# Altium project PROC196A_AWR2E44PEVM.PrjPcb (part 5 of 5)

## Sheet PROC196A_CAN_Interface.SchDoc
size 431 x 279 mm; Date: Not shown in title block; ApprovedBy: Not shown in title block; CheckedBy: Not shown in title block; Author: Not shown in title block; CompanyName: Not shown in title block; Engineer: Not shown in title block; Organization: Not shown in title block; Address1: Not shown in title block; Address2: Not shown in title block; Address3: Not shown in title block; Address4: Not shown in title block; DocumentNumber: 22; Revision: Use project parameter SCH_Rev; SheetNumber: 22; SheetTotal: 25; PageSetup: Record=PageOptions¦CenterHorizontal=True¦CenterVertical=True¦PrintScale=1.00¦XCorrection=1.00¦YCorrection=1.00¦PrintKind=0¦BorderSize=5000000¦LeftOffset=0¦BottomOffset=0¦Orientation=2¦PaperLength=1000¦PaperWidth=1000¦Scale=100¦PaperSource=15¦PrintQuality=600¦MediaType=1¦DitherType=10¦PaperKind=Letter¦PrintScaleMode=1
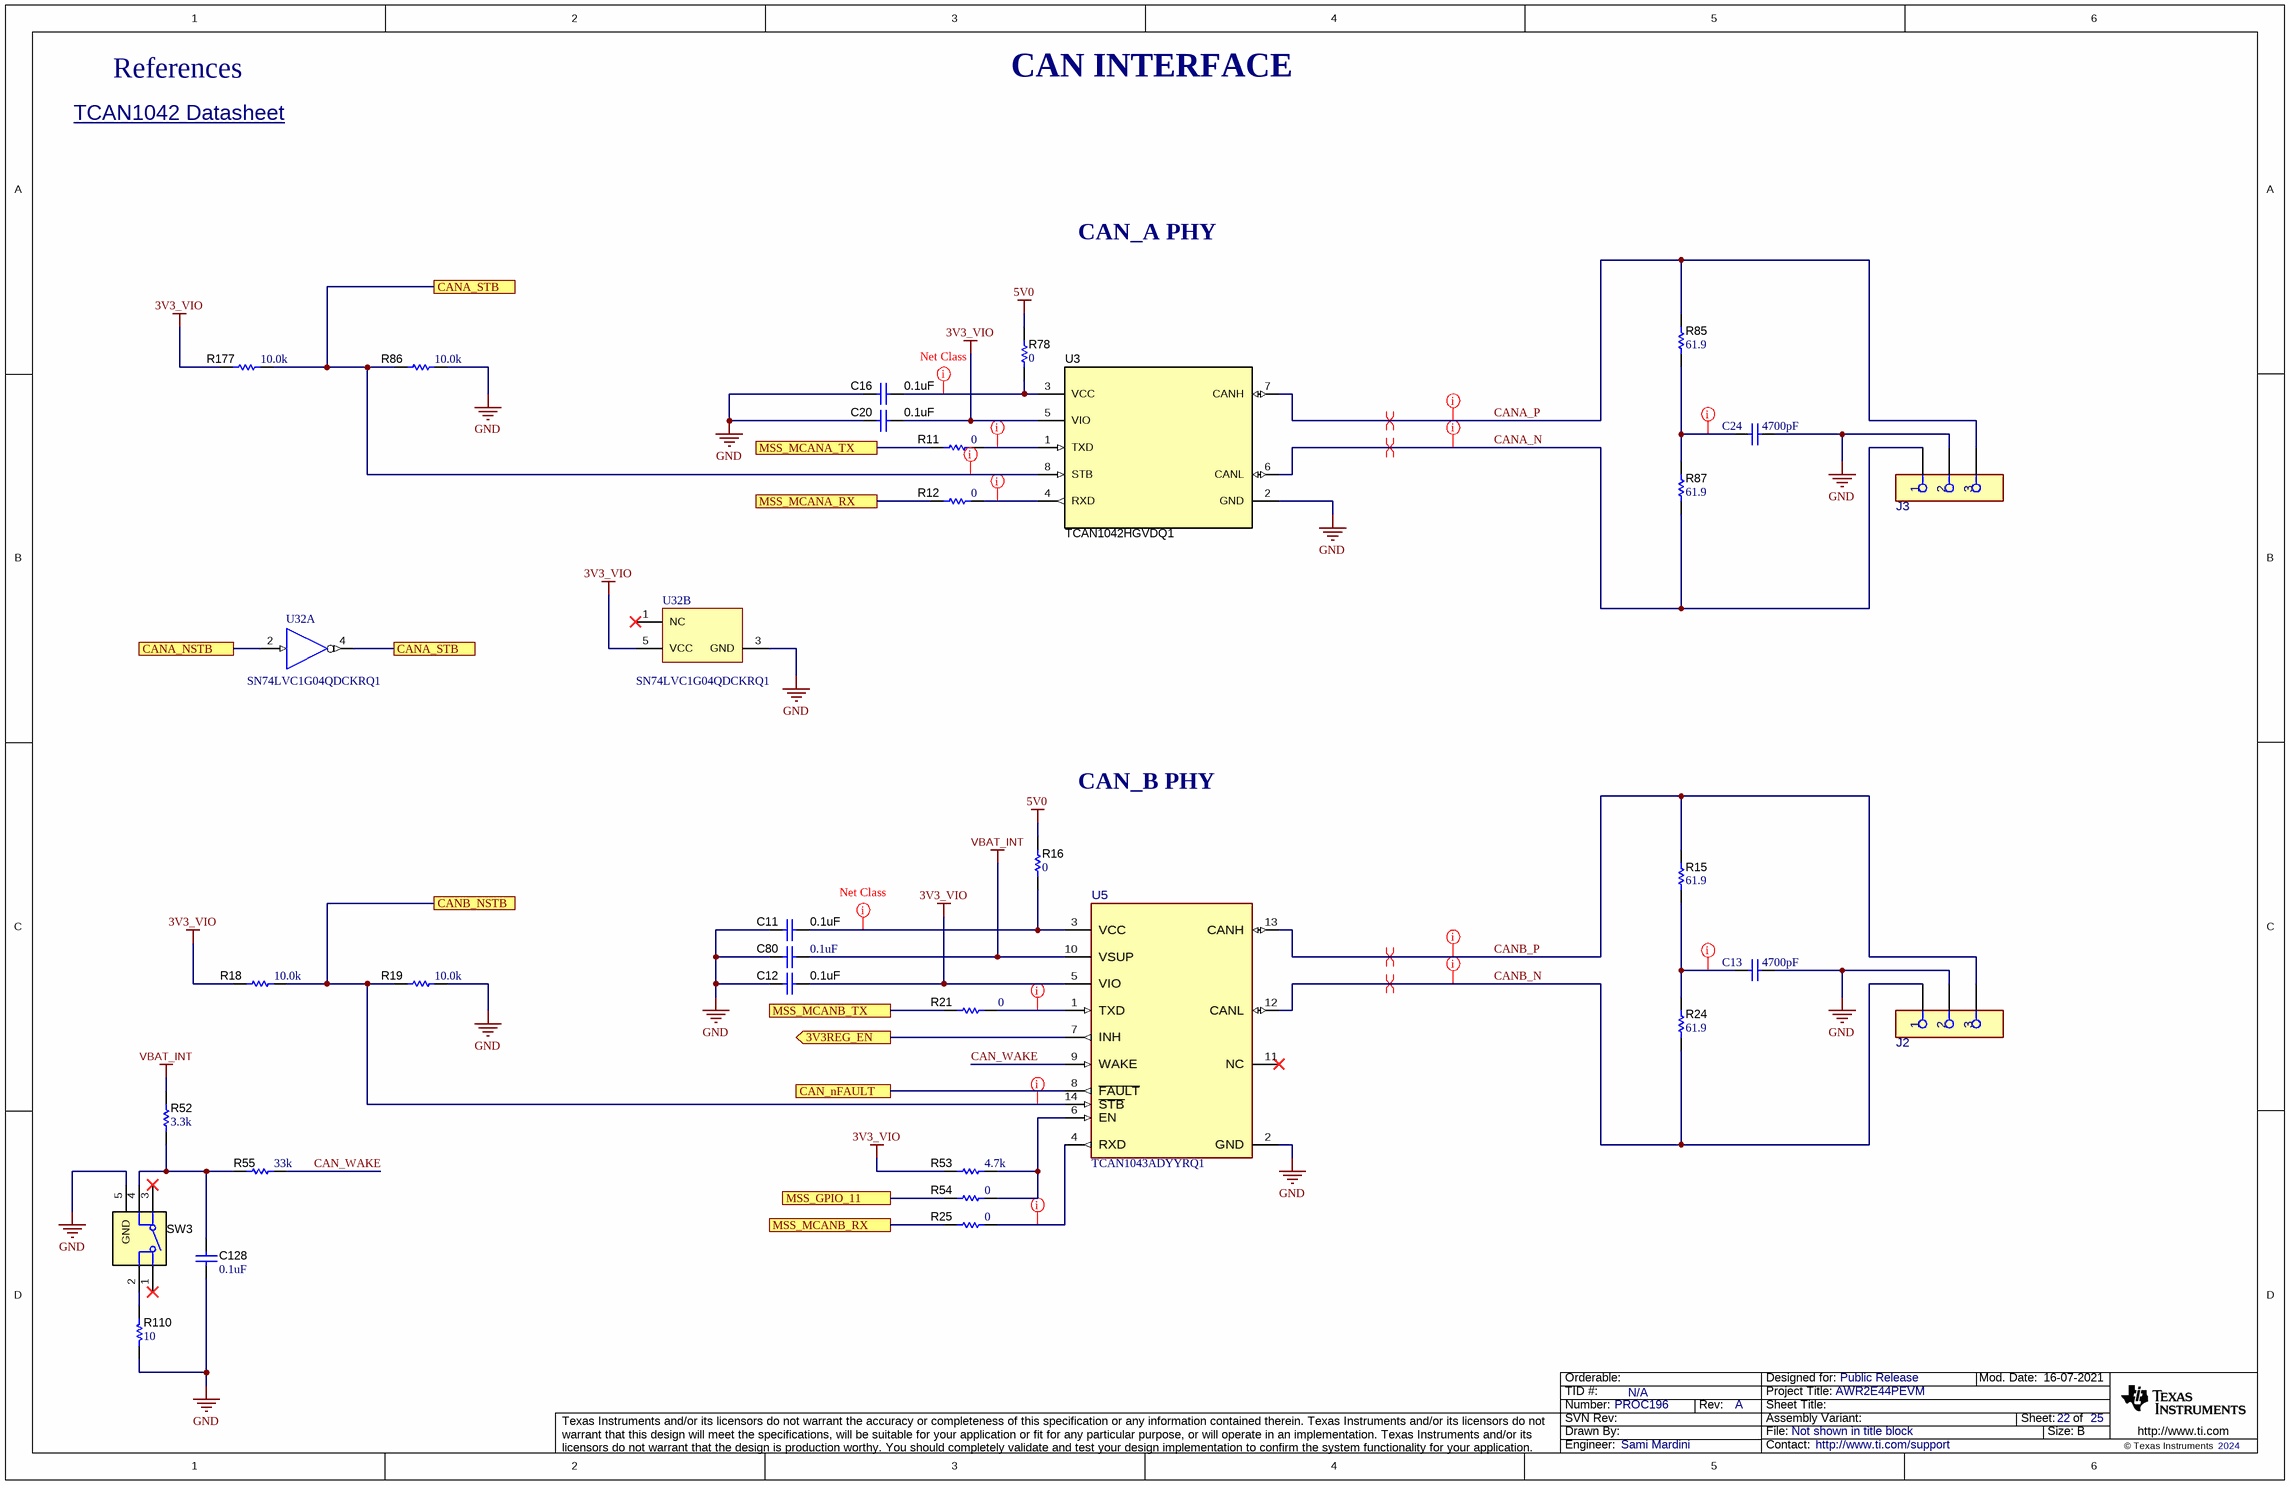
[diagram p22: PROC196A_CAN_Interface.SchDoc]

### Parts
C11  ValueDisplayed: 0.1uF  [0402L]  (hidden comment: GCM155R71C104KA55D)
C12  ValueDisplayed: 0.1uF  [0402L]  (hidden comment: GCM155R71C104KA55D)
C13  ValueDisplayed: 4700pF  [0402L]  (hidden comment: GCM155R71H472KA37D)
C16  ValueDisplayed: 0.1uF  [0402L]  (hidden comment: GCM155R71C104KA55D)
C20  ValueDisplayed: 0.1uF  [0402L]  (hidden comment: GCM155R71C104KA55D)
C24  ValueDisplayed: 4700pF  [0402L]  (hidden comment: GCM155R71H472KA37D)
C80  ValueDisplayed: 0.1uF  [0402L]  (hidden comment: CGA2B3X7R1H104K050BB)
C128  ValueDisplayed: 0.1uF  [0402L]  (hidden comment: CGA2B3X7R1H104K050BB)
J2  OSTTF030161  [FP-OSTTF030161_PTH_TERMINAL_BLOCK-MFG]  (value not drawn)
J3  OSTTF030161  [FP-OSTTF030161_PTH_TERMINAL_BLOCK-MFG]  (value not drawn)
R11  value 0  [0402L]  (hidden comment: ERJ-2GE0R00X)
R12  ValueDisplayed: 0  [0402L]  (hidden comment: ERJ-2GE0R00X)
R15  ValueDisplayed: 61.9  [0402L]  (hidden comment: CRCW040261R9FKED)
R16  ValueDisplayed: 0  [0402L]  (hidden comment: ERJ-2GE0R00X)
R18  ValueDisplayed: 10.0k  [0402L]  (hidden comment: CRCW040210K0FKED)
R19  ValueDisplayed: 10.0k  [0402L]  (hidden comment: CRCW040210K0FKED)
R21  value 0  [0402L]  (hidden comment: ERJ-2GE0R00X)
R24  ValueDisplayed: 61.9  [0402L]  (hidden comment: CRCW040261R9FKED)
R25  ValueDisplayed: 0  [0402L]  (hidden comment: ERJ-2GE0R00X)
R52  ValueDisplayed: 3.3k  [0402L]  (hidden comment: CRCW04023K30JNED)
R53  ValueDisplayed: 4.7k  [0402L]  (hidden comment: CRCW04024K70JNED)
R54  ValueDisplayed: 0  [0402L]  (hidden comment: ERJ-2GE0R00X)
R55  ValueDisplayed: 33k  [0402L]  (hidden comment: CRCW040233K0JNED)
R78  ValueDisplayed: 0  [0402L]  (hidden comment: ERJ-2GE0R00X)
R85  ValueDisplayed: 61.9  [0402L]  (hidden comment: CRCW040261R9FKED)
R86  ValueDisplayed: 10.0k  [0402L]  (hidden comment: CRCW040210K0FKED)
R87  ValueDisplayed: 61.9  [0402L]  (hidden comment: CRCW040261R9FKED)
R110  ValueDisplayed: 10  [0402L]  (hidden comment: CRCW040210R0JNED)
R177  ValueDisplayed: 10.0k  [0402L]  (hidden comment: CRCW040210K0FKED)
SW3  KMR243GLFG  [SW_KMR243GLFG]  (value not drawn)
U3  TCAN1042HGVDQ1  [D0008A_L]
U5  TCAN1043ADYYRQ1  [DYY0014A-MFG]
U32  SN74LVC1G04QDCKRQ1  [DCK0005A_N]  (parts A,B of 2)

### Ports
3V3REG_EN (out), CAN_nFAULT, CANA_NSTB, CANA_STB, CANB_NSTB, MSS_GPIO_11, MSS_MCANA_RX, MSS_MCANA_TX, MSS_MCANB_RX, MSS_MCANB_TX

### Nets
3V3_VIO: C12.2 C20.2 R18.1 R53.1 R177.1 U3.5(VIO) U5.5(VIO) U32.5(VCC)
5V0: R16.2 R78.2
GND: C11.1 C12.1 C13.1 C16.1 C20.1 C24.1 C80.2 C128.2 J2.2 J3.2 R19.2 R86.2 R110.1 SW3.5(GND) U3.2(GND) U5.2(GND) U32.3(GND)
VBAT_INT: C80.1 R52.2 U5.10(VSUP)
3V3REG_EN: U5.7(INH) ; port 3V3REG_EN
CAN_nFAULT: U5.8(~{FAULT}) ; port CAN_nFAULT
CAN_WAKE: R55.1 U5.9(WAKE)
CANA_N: J3.1 R87.1 U3.6(CANL)
CANA_NSTB: U32.2(A) ; port CANA_NSTB
CANA_P: J3.3 R85.2 U3.7(CANH)
CANA_STB: R86.1 R177.2 U3.8(STB) U32.4(Y) ; port CANA_STB
CANB_N: J2.1 R24.1 U5.12(CANL)
CANB_NSTB: R18.2 R19.1 U5.14(~{STB}) ; port CANB_NSTB
CANB_P: J2.3 R15.2 U5.13(CANH)
MSS_GPIO_11: R54.1 ; port MSS_GPIO_11
MSS_MCANA_RX: R12.1 ; port MSS_MCANA_RX
MSS_MCANA_TX: R11.1 ; port MSS_MCANA_TX
MSS_MCANB_RX: R25.1 ; port MSS_MCANB_RX
MSS_MCANB_TX: R21.1 ; port MSS_MCANB_TX
NetC11_2: C11.2 R16.1 U5.3(VCC)
NetC13_2: C13.2 R15.1 R24.2
NetC16_2: C16.2 R78.1 U3.3(VCC)
NetC24_2: C24.2 R85.1 R87.2
NetC128_1: C128.1 R52.1 R55.2 SW3.4
NetR11_2: R11.2 U3.1(TXD)
NetR12_2: R12.2 U3.4(RXD)
NetR21_2: R21.2 U5.1(TXD)
NetR25_2: R25.2 U5.4(RXD)
NetR53_2: R53.2 R54.2 U5.6(EN)
NetR110_2: R110.2 SW3.2

Not connected (* = marked no-connect by the designer): SW3 1* 3*; U5 11(NC)*; U32 1(NC)*

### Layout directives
net class CAN: CANA_STB, CANB_NSTB, NetR11_2, NetR12_2, NetR21_2, NetR25_2
net class CAN; net class CAN_DIFF: CANA_N, CANA_P, CANB_N, CANB_P
net class CAN; net class PWR: NetC13_2, NetC24_2
net class PWR: NetC11_2, NetC16_2
differential pair: CANA_N, CANA_P, CANB_N, CANB_P

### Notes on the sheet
- References
- CAN INTERFACE
- TCAN1042 Datasheet <http://www.ti.com/lit/ds/symlink/tcan1042gv-q1.pdf>
- CAN_A PHY
- CAN_B PHY

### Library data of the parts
C11 C12 C16 C20 = CMP-0006351-2: CAP, CERM, 0.1 uF, 16 V, +/- 10%, X7R, 0402; Manufacturer: MuRata; TaMin_C: -55°C; Polarized: N; SizeAreaWB_mm2: 3; Value1: Unknown; U/M: EA; Value: 0.1uF; TaMax_C: 125°C; SizeZ_mm: 0.6; SizeX_mm: 1; SizeY_mm: 0.5; Cap_Case: 0402; Value2: 16V; Cap_F: 100nF; AEC Category: Q200
C13 C24 = CMP-0006361-2: CAP, CERM, 4700 pF, 50 V, +/- 10%, X7R, AEC-Q200 Grade 1, 0402; Manufacturer: MuRata; TaMin_C: -55°C; Polarized: N; SizeAreaWB_mm2: 3; Value1: Unknown; U/M: EA; Value: 4700pF; TaMax_C: 125°C; SizeZ_mm: 0.6; SizeX_mm: 1; SizeY_mm: 0.5; Cap_Case: 0402; Value2: 50V; AEC Qualified: Y; Cap_F: 4.7nF; AEC Category: Q200
C80 C128 = CMP-0006325-2: CAP, CERM, 0.1 uF, 50 V, +/- 10%, X7R, AEC-Q200 Grade 1, 0402; Manufacturer: TDK; TaMin_C: -55°C; ESR_ohm: 0.039064; Polarized: N; SizeAreaWB_mm2: 3; Value1: 0.039064 ohm; U/M: EA; Value: 0.1uF; TaMax_C: 125°C; SizeZ_mm: 0.6; SizeX_mm: 1; SizeY_mm: 0.5; Cap_Case: 0402; Value2: 50V; AEC Qualified: Y; Cap_F: 100nF; IRMS_A: 8.14669dA; AEC Category: Q200
J2 J3 = CMP-0091742-1: 3 Position Wire to Board Terminal Block Vertical with Board 0.138" (3.50mm) Through Hole; Manufacturer: On Shore Technology; Voltage_V: 150V; Row_Count: 1; DUT-Pitch_mm: 3.5mm; Current_A: 10A; Min Wire Gauge: 30; ContactFinish: Tin; AEC Qualified: No; Conn Gender: Female; Is Female: yes; Max Wire Gauge: 16; SizeZ_mm: 7.3mm
R11 R21 = CMP-0026992-3: RES, 0, 5%, 0.1 W, AEC-Q200 Grade 0, 0402; Manufacturer: Panasonic; Power_W: 100mW; TempCo: 600 ppm/C; Value_Code: 0000; EIA_Code: E24; SizeX_mm: 1; SizeY_mm: 0.5; SizeZ_mm: 0.6; Value2: 0.1W; AEC Qualified: Y; VDC_V: 50V; AEC Category: Q200; SizeAreaWB_mm2: 3
R12 R16 R25 R54 R78 = CMP-0026992-3: RES, 0, 5%, 0.1 W, AEC-Q200 Grade 0, 0402; Manufacturer: Panasonic; Power_W: 100mW; TempCo: 600 ppm/C; Value_Code: 0000; Value: 0; EIA_Code: E24; SizeX_mm: 1; SizeY_mm: 0.5; SizeZ_mm: 0.6; Value2: 0.1W; AEC Qualified: Y; VDC_V: 50V; AEC Category: Q200; SizeAreaWB_mm2: 3
R15 R24 R85 R87 = CMP-0026491-2: RES, 61.9, 1%, 0.063 W, AEC-Q200 Grade 0, 0402; Manufacturer: Vishay-Dale; Power_W: 63mW; TempCo: 100 ppm/C; Value_Code: 61R9; Value: 61.9; EIA_Code: E96; SizeX_mm: 1; SizeY_mm: 0.5; SizeZ_mm: 0.6; Value2: 0.063W; AEC Qualified: Y; VDC_V: 50V; AEC Category: Q200; AEC Grade: 0
R18 R19 R86 R177 = CMP-0025958-3: RES, 10.0 k, 1%, 0.063 W, AEC-Q200 Grade 0, 0402; Manufacturer: Vishay-Dale; Power_W: 63mW; TempCo: 100 ppm/C; Value_Code: 10k0; Value: 10.0k; EIA_Code: E96; Res_ohm: 10k; SizeX_mm: 1; SizeY_mm: 0.5; SizeZ_mm: 0.6; Value2: 0.063W; AEC Qualified: Y; VDC_V: 50V; AEC Category: Q200; AEC Grade: 0
R52 = CMP-0026918-5: RES, 3.3 k, 5%, 0.063 W, AEC-Q200 Grade 0, 0402; Manufacturer: Vishay-Dale; Power_W: 63mW; TempCo: 200 ppm/C; Value_Code: 3k30; Value: 3.3k; EIA_Code: E24; SizeX_mm: 1; SizeY_mm: 0.5; SizeZ_mm: 0.6; Value2: 0.063W; AEC Qualified: Y; VDC_V: 50V; AEC Category: Q200; AEC Grade: 0
R53 = CMP-0026938-5: RES, 4.7 k, 5%, 0.063 W, AEC-Q200 Grade 0, 0402; Manufacturer: Vishay-Dale; Power_W: 63mW; TempCo: 200 ppm/C; Value_Code: 4k70; Value: 4.7k; EIA_Code: E24; SizeX_mm: 1; SizeY_mm: 0.5; SizeZ_mm: 0.6; Value2: 0.063W; AEC Qualified: Y; VDC_V: 50V; AEC Category: Q200; AEC Grade: 0
R55 = CMP-0026907-3: RES, 33 k, 5%, 0.063 W, AEC-Q200 Grade 0, 0402; Manufacturer: Vishay-Dale; Power_W: 63mW; TempCo: 200 ppm/C; Value_Code: 33k0; Value: 33k; EIA_Code: E24; SizeX_mm: 1; SizeY_mm: 0.5; SizeZ_mm: 0.6; Value2: 0.063W; AEC Qualified: Y; VDC_V: 50V; AEC Category: Q200; AEC Grade: 0
R110 = CMP-0026827-3: RES, 10, 5%, 0.063 W, AEC-Q200 Grade 0, 0402; Manufacturer: Vishay-Dale; Power_W: 63mW; TempCo: 200 ppm/C; Value_Code: 10R0; Value: 10; EIA_Code: E24; SizeX_mm: 1; SizeY_mm: 0.5; SizeZ_mm: 0.6; Value2: 0.063W; AEC Qualified: Y; VDC_V: 50V; AEC Category: Q200; AEC Grade: 0
SW3 = CMP-0002325-1: Switch, SPST-NO, Off-Mom, 0.01 A, 32 VDC, SMD; Manufacturer: C&K Components; CurrentRating_mA: 10A; PositionCount: 1; SizeX_mm: 4.6; SizeY_mm: 2.8; SizeZ_mm: 1.9; SizeArea_mm2: 12.88; VDC_V: 32V; SizeAreaWB_mm2: 21.28
U3 = CMP-0075992-1: Automotive Fault Protected CAN Transceiver With Flexible Data-Rate, D0008A (SOIC-8); Manufacturer: Texas Instruments; Alternate PartNumber: TCAN1042HGVDRQ1; SizeAreaWB_mm2: 56.58; SizeArea_mm2: 30.38; SizeZ_mm: 1.75; SizeY_mm: 6.2; U/M: EA; CompType: IC; SizeX_mm: 4.9
U5 = CMP-0089855-1: Low-Power Fault Protected CAN FD Transceiver with INH and WAKE; Manufacturer: Texas Instruments; Max Supply Voltage: 28V; Standoff Height: 0mm; Min Supply Voltage: 1.7V; AEC Grade: Grade 1; SizeZ_mm: 1.1mm; TJmax_C: +165°C; AEC Qualified: Yes
U32 = CMP-0051661-3: Automotive Catalog Single Inverter, DCK0005A, LARGE T&R; Manufacturer: Texas Instruments; Generic Part Number: SN74LVC1G04-Q1; Logic: Inverting; Input Type: CMOS/TTL; 3-State Output: No; Voltage(Nom)(V): 1.8,2.5,3.3,5; tpd @ Nom Voltage(Max)(ns): 7.5,5.2,4.2,3.7; Sub-Family: Inverting Buffer/Driver; Bits(#): 1; VCC(Min)(V): 1.65; F @ Nom Voltage(Max)(Mhz): 150; ICC @ Nom Voltage(Max)(mA): 0.01; Technology Family: LVC; Output Drive (IOL/IOH)(Max)(mA): 32/-32; Output Type: CMOS; VCC(Max)(V): 5.5; AEC Category: Q200; AEC Qualified: Y; CompType: IC; SizeAreaWB_mm2: 9.3; SizeArea_mm2: 4.2; SizeX_mm: 2.1; SizeY_mm: 2.0; SizeZ_mm: 1.1

## Sheet PROC196A_Current_Sensors.SchDoc
size 431 x 279 mm; Date: Not shown in title block; ApprovedBy: Not shown in title block; CheckedBy: Not shown in title block; Author: Not shown in title block; CompanyName: Not shown in title block; Engineer: Not shown in title block; Organization: Not shown in title block; Address1: Not shown in title block; Address2: Not shown in title block; Address3: Not shown in title block; Address4: Not shown in title block; DocumentNumber: 23; Revision: Use project parameter SCH_Rev; SheetNumber: 23; SheetTotal: 25; PageSetup: Record=PageOptions¦CenterHorizontal=True¦CenterVertical=True¦PrintScale=1.00¦XCorrection=1.00¦YCorrection=1.00¦PrintKind=0¦BorderSize=5000000¦LeftOffset=0¦BottomOffset=0¦Orientation=2¦PaperLength=1000¦PaperWidth=1000¦Scale=100¦PaperSource=15¦PrintQuality=600¦MediaType=1¦DitherType=10¦PaperKind=Letter¦PrintScaleMode=1
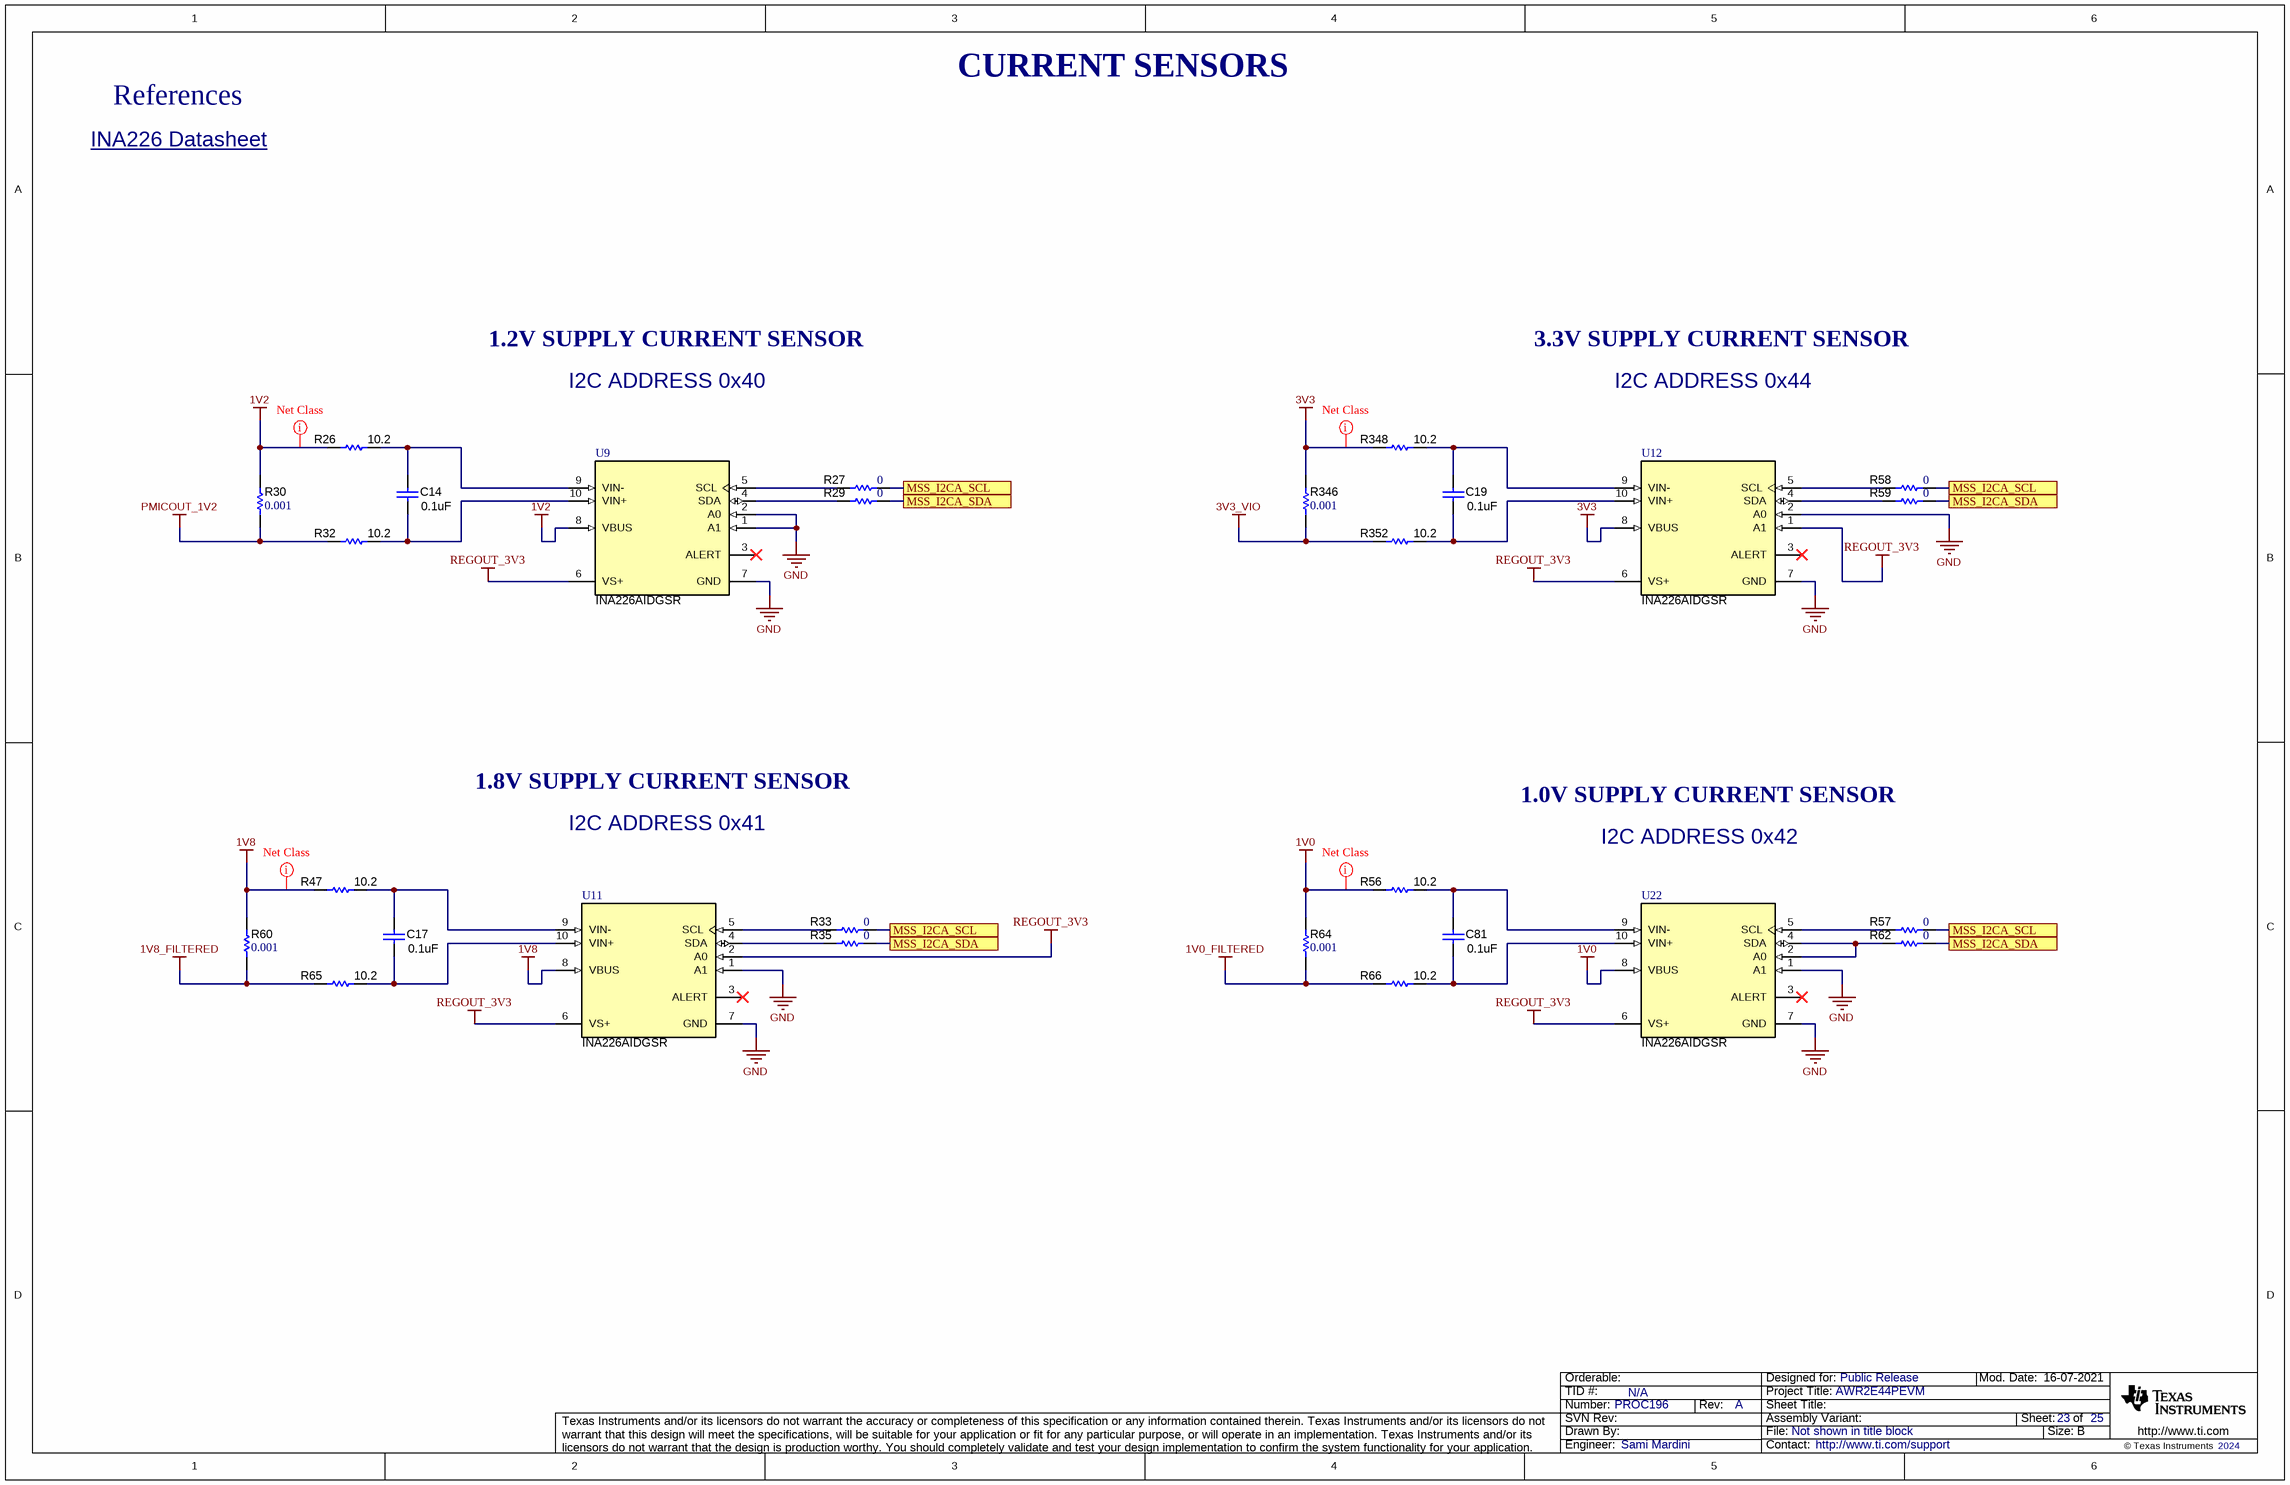
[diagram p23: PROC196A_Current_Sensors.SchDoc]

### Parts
C14  ValueDisplayed: 0.1uF  [0402L]  (hidden comment: GCM155R71A104KA55D)
C17  ValueDisplayed: 0.1uF  [0402L]  (hidden comment: GCM155R71A104KA55D)
C19  ValueDisplayed: 0.1uF  [0402L]  (hidden comment: GCM155R71A104KA55D)
C81  ValueDisplayed: 0.1uF  [0402L]  (hidden comment: GCM155R71A104KA55D)
R26  ValueDisplayed: 10.2  [0402L]  (hidden comment: CRCW040210R2FKED)
R27  ValueDisplayed: 0  [0402L]  (hidden comment: ERJ-2GE0R00X)
R29  ValueDisplayed: 0  [0402L]  (hidden comment: ERJ-2GE0R00X)
R30  ValueDisplayed: 0.001  [1206L]  (hidden comment: CSNL1206FT1L00)
R32  ValueDisplayed: 10.2  [0402L]  (hidden comment: CRCW040210R2FKED)
R33  ValueDisplayed: 0  [0402L]  (hidden comment: ERJ-2GE0R00X)
R35  ValueDisplayed: 0  [0402L]  (hidden comment: ERJ-2GE0R00X)
R47  ValueDisplayed: 10.2  [0402L]  (hidden comment: CRCW040210R2FKED)
R56  ValueDisplayed: 10.2  [0402L]  (hidden comment: CRCW040210R2FKED)
R57  ValueDisplayed: 0  [0402L]  (hidden comment: ERJ-2GE0R00X)
R58  ValueDisplayed: 0  [0402L]  (hidden comment: ERJ-2GE0R00X)
R59  ValueDisplayed: 0  [0402L]  (hidden comment: ERJ-2GE0R00X)
R60  ValueDisplayed: 0.001  [1206L]  (hidden comment: CSNL1206FT1L00)
R62  ValueDisplayed: 0  [0402L]  (hidden comment: ERJ-2GE0R00X)
R64  ValueDisplayed: 0.001  [1206L]  (hidden comment: CSNL1206FT1L00)
R65  ValueDisplayed: 10.2  [0402L]  (hidden comment: CRCW040210R2FKED)
R66  ValueDisplayed: 10.2  [0402L]  (hidden comment: CRCW040210R2FKED)
R346  ValueDisplayed: 0.001  [1206L]  (hidden comment: CSNL1206FT1L00)
R348  ValueDisplayed: 10.2  [0402L]  (hidden comment: CRCW040210R2FKED)
R352  ValueDisplayed: 10.2  [0402L]  (hidden comment: CRCW040210R2FKED)
U9  INA226AIDGSR  [DGS0010A_L]
U11  INA226AIDGSR  [DGS0010A_L]
U12  INA226AIDGSR  [DGS0010A_L]
U22  INA226AIDGSR  [DGS0010A_L]

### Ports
MSS_I2CA_SCL, MSS_I2CA_SDA

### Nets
1V0: R56.1 R64.2 U22.8(VBUS)
1V0_FILTERED: R64.1 R66.1
1V2: R26.1 R30.2 U9.8(VBUS)
1V8: R47.1 R60.2 U11.8(VBUS)
1V8_FILTERED: R60.1 R65.1
3V3: R346.2 R348.1 U12.8(VBUS)
3V3_VIO: R346.1 R352.1
GND: U9.1(A1) U9.2(A0) U9.7(GND) U11.1(A1) U11.7(GND) U12.2(A0) U12.7(GND) U22.1(A1) U22.7(GND)
PMICOUT_1V2: R30.1 R32.1
REGOUT_3V3: U9.6(VS+) U11.2(A0) U11.6(VS+) U12.1(A1) U12.6(VS+) U22.6(VS+)
MSS_I2CA_SCL: R27.2 R33.2 R57.2 R58.2 ; port MSS_I2CA_SCL
MSS_I2CA_SDA: R29.2 R35.2 R59.2 R62.2 ; port MSS_I2CA_SDA
NetC14_1: C14.1 R26.2 U9.9(VIN-)
NetC14_2: C14.2 R32.2 U9.10(VIN+)
NetC17_1: C17.1 R47.2 U11.9(VIN-)
NetC17_2: C17.2 R65.2 U11.10(VIN+)
NetC19_1: C19.1 R348.2 U12.9(VIN-)
NetC19_2: C19.2 R352.2 U12.10(VIN+)
NetC81_1: C81.1 R56.2 U22.9(VIN-)
NetC81_2: C81.2 R66.2 U22.10(VIN+)
NetR27_1: R27.1 U9.5(SCL)
NetR29_1: R29.1 U9.4(SDA)
NetR33_1: R33.1 U11.5(SCL)
NetR35_1: R35.1 U11.4(SDA)
NetR57_1: R57.1 U22.5(SCL)
NetR58_1: R58.1 U12.5(SCL)
NetR59_1: R59.1 U12.4(SDA)
NetR62_1: R62.1 U22.2(A0) U22.4(SDA)

Not connected (* = marked no-connect by the designer): U9 3(ALERT)*; U11 3(ALERT)*; U12 3(ALERT)*; U22 3(ALERT)*

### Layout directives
net class PWR: 1V0, 1V2, 1V8, 3V3

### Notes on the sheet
- CURRENT SENSORS
- References
- INA226 Datasheet <http://www.ti.com/lit/ds/symlink/ina226.pdf>
- 1.2V SUPPLY CURRENT SENSOR
- 3.3V SUPPLY CURRENT SENSOR
- I2C ADDRESS 0x40
- I2C ADDRESS 0x44
- 1.8V SUPPLY CURRENT SENSOR
- I2C ADDRESS 0x41
- 1.0V SUPPLY CURRENT SENSOR
- I2C ADDRESS 0x42

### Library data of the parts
C14 C17 C19 C81 = CMP-0006350-2: CAP, CERM, 0.1 uF, 10 V, +/- 10%, X7R, AEC-Q200 Grade 1, 0402; Manufacturer: MuRata; TaMin_C: -55°C; Polarized: N; SizeAreaWB_mm2: 3; Value1: Unknown; U/M: EA; Value: 0.1uF; TaMax_C: 125°C; SizeZ_mm: 0.6; SizeX_mm: 1; SizeY_mm: 0.5; Cap_Case: 0402; Value2: 10V; AEC Qualified: Y; Cap_F: 100nF; AEC Category: Q200
R26 R32 R47 R56 R65 R66 R348 R352 = CMP-0025964-3: RES, 10.2, 1%, 0.063 W, AEC-Q200 Grade 0, 0402; Manufacturer: Vishay-Dale; Power_W: 63mW; TempCo: 100 ppm/C; Value_Code: 10R2; Value: 10.2; EIA_Code: E96; SizeX_mm: 1; SizeY_mm: 0.5; SizeZ_mm: 0.6; Value2: 0.063W; AEC Qualified: Y; VDC_V: 50V; AEC Category: Q200; AEC Grade: 0
R27 R29 R33 R35 R57-R59 R62 = CMP-0026992-3: as R12 on sheet PROC196A_CAN_Interface
R30 R60 R64 R346 = CMP-0017253-2: RES, 0.001, 1%, 1 W, AEC-Q200 Grade 0, 1206; Manufacturer: Stackpole Electronics Inc; Power_W: 1W; TempCo: 50 ppm/C; Value_Code: 1L000; U/M: EA; Value: 0.001; EIA_Code: E96; Res_ohm: 1m; SizeX_mm: 3.2; SizeY_mm: 1.6; SizeZ_mm: 1.35; SizeArea_mm2: 5.12; AEC Qualified: Y; AEC Grade: 0; AEC Category: Q200
U9 U11 U12 U22 = CMP-0037979-1: High-Side Measurement, Bi-Directional Current / Power Monitor with I2C Interface, 2.7 to 5.5 V, -40 to 125 degC, 10-pin SOP (DGS10), Green (RoHS & no Sb/Br); Manufacturer: Texas Instruments; Common Mode Range(Max)(V): 36; Vs(Min)(V): 2.7; SubFamily: Current Shunt Monitor; Small-Signal Bandwidth(Typ)(MHz): 0.007; CMRR(Min)(dB): 126; Gain(V/V): 1; Vs(Max)(V): 5.5; Rating: Catalog; Input Offset Drift (+/-)(Max)(uV/Degrees Celsius): 0.1; Quiescent Current (+/-)(Typ)(mA): 0.33; Common Mode Range(Min)(V): 0; Input Offset (+/-)(Max)(uV): 10

## Sheet PROC196A_Temp_Sensor.SchDoc
size 431 x 279 mm; Date: Not shown in title block; ApprovedBy: Not shown in title block; CheckedBy: Not shown in title block; Author: Not shown in title block; CompanyName: Not shown in title block; Engineer: Not shown in title block; Organization: Not shown in title block; Address1: Not shown in title block; Address2: Not shown in title block; Address3: Not shown in title block; Address4: Not shown in title block; DocumentNumber: 24; Revision: Use project parameter SCH_Rev; SheetNumber: 24; SheetTotal: 25; PageSetup: Record=PageOptions¦CenterHorizontal=True¦CenterVertical=True¦PrintScale=1.00¦XCorrection=1.00¦YCorrection=1.00¦PrintKind=0¦BorderSize=5000000¦LeftOffset=0¦BottomOffset=0¦Orientation=2¦PaperLength=1000¦PaperWidth=1000¦Scale=100¦PaperSource=15¦PrintQuality=600¦MediaType=1¦DitherType=10¦PaperKind=Letter¦PrintScaleMode=1
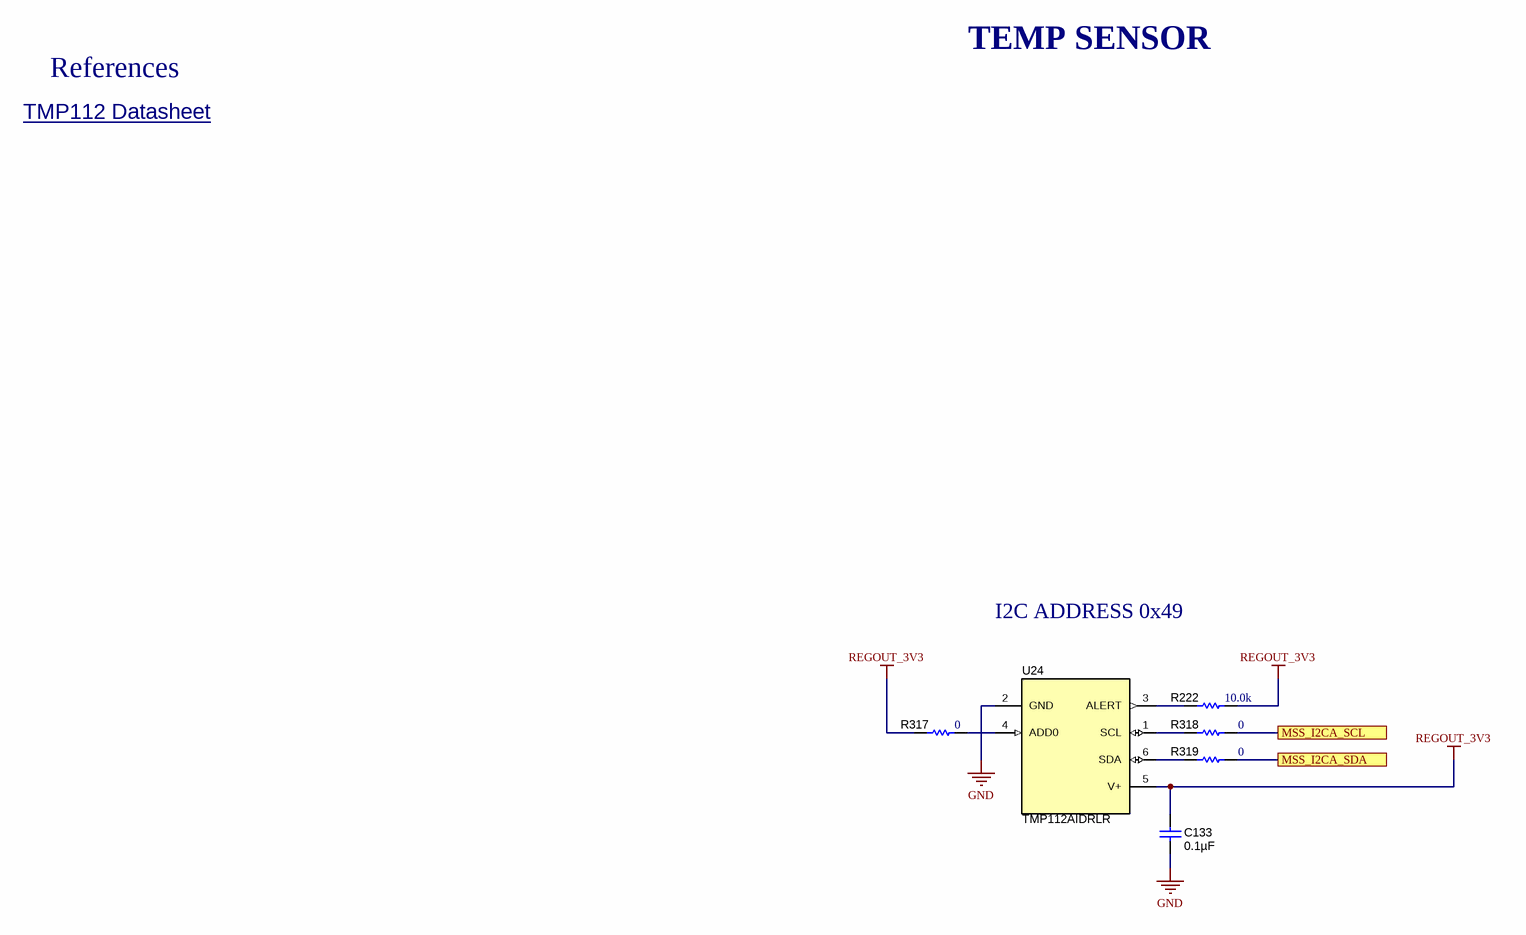
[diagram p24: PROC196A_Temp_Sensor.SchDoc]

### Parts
C133  ValueDisplayed: 0.1µF  [0402L]  (hidden comment: C0402C104K8RACTU)
R222  ValueDisplayed: 10.0k  [0402L]  (hidden comment: CRCW040210K0FKED)
R317  ValueDisplayed: 0  [0201L]  (hidden comment: CRCW02010000Z0ED)
R318  ValueDisplayed: 0  [0201L]  (hidden comment: CRCW02010000Z0ED)
R319  ValueDisplayed: 0  [0201L]  (hidden comment: CRCW02010000Z0ED)
U24  TMP112AIDRLR  [DRL0006A]

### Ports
MSS_I2CA_SCL, MSS_I2CA_SDA

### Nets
GND: C133.2 U24.2(GND)
REGOUT_3V3: C133.1 R222.2 R317.1 U24.5(V+)
MSS_I2CA_SCL: R318.1 ; port MSS_I2CA_SCL
MSS_I2CA_SDA: R319.2 ; port MSS_I2CA_SDA
NetR222_1: R222.1 U24.3(ALERT)
NetR317_2: R317.2 U24.4(ADD0)
NetR318_2: R318.2 U24.1(SCL)
NetR319_1: R319.1 U24.6(SDA)

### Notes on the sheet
- TEMP SENSOR
- References
- TMP112 Datasheet <http://www.ti.com/lit/ds/symlink/tmp112.pdf>
- I2C ADDRESS 0x49

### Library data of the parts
C133 = CMP-0078241-1: CAP, CERM, 0.1 µF, 10 V,+/- 10%, X7R, 0402; Manufacturer: Kemet; TaMin_C: -55°C; Polarized: N; SizeAreaWB_mm2: 3; U/M: EA; Value: 0.1uF; TaMax_C: 125°C; SizeZ_mm: 0.6; SizeX_mm: 1; SizeY_mm: 0.5; Cap_Case: 0402; Value2: 10V; Cap_F: 100nF; AEC Category: Q200
R222 = CMP-0025958-3: as R18 on sheet PROC196A_CAN_Interface
R317-R319 = CMP-0027008-4: RES, 0, 5%, 0.05 W, 0201; Manufacturer: Vishay-Dale; Power_W: 50mW; TempCo: ppm/C; Value_Code: 0000; Value: 0; EIA_Code: E24; SizeX_mm: 0.6; SizeY_mm: 0.3; SizeZ_mm: 0.26; Value2: 0.05W; SizeArea_mm2: 0.18; AEC Qualified: N; AEC Category: Q200
U24 = CMP-0067397-2: 1.4V-Capable +/-0.5degC Temperature Sensor with Alert Function and I2C/SMBus interface in SOT-563, DRL0006A (SOT-OTHER-6); Alternate PartNumber: TMP112AIDRLT; Alternate Manufacturer: Texas Instruments; Green_Lifecycle: Active; SizeAreaWB_mm2: 6.76; Green_REACh: Passed; U/M: EA; SizeZ_mm: 0.6; SizeX_mm: 1.6; SizeArea_mm2: 2.56; CompType: IC

## Sheet PROC196A_Hardware.SchDoc
size 431 x 279 mm; Date: Not shown in title block; ApprovedBy: Not shown in title block; CheckedBy: Not shown in title block; Author: Not shown in title block; CompanyName: Not shown in title block; Engineer: Not shown in title block; Organization: Not shown in title block; Address1: Not shown in title block; Address2: Not shown in title block; Address3: Not shown in title block; Address4: Not shown in title block; DocumentNumber: 25; Revision: Use project parameter SCH_Rev; SheetNumber: 25; SheetTotal: 25; PageSetup: Record=PageOptions¦CenterHorizontal=True¦CenterVertical=True¦PrintScale=1.00¦XCorrection=1.00¦YCorrection=1.00¦PrintKind=0¦BorderSize=5000000¦LeftOffset=0¦BottomOffset=0¦Orientation=2¦PaperLength=1000¦PaperWidth=1000¦Scale=100¦PaperSource=15¦PrintQuality=600¦MediaType=1¦DitherType=10¦PaperKind=Letter¦PrintScaleMode=1
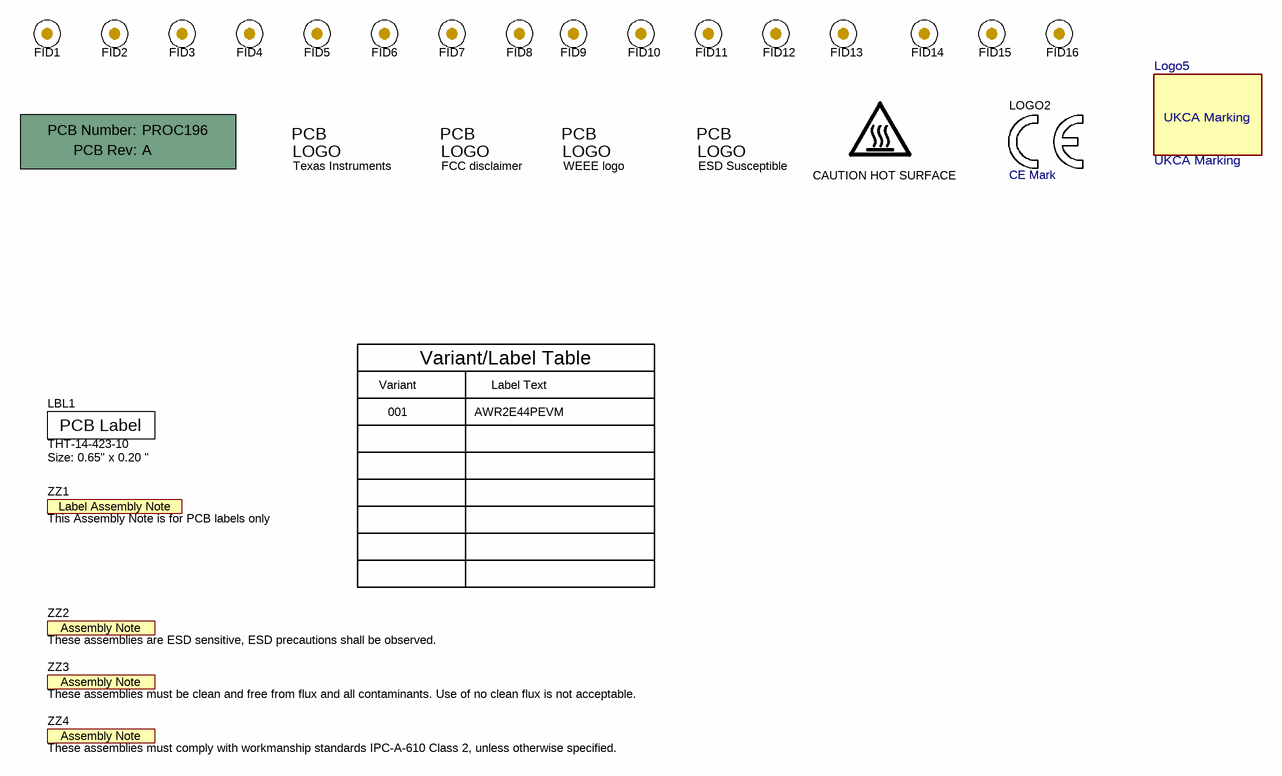
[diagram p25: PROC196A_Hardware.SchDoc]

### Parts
!PCB  Printed Circuit Board  (value not drawn)  (mechanical)
CAUTION_HOT_SURFACE1  CAUTION HOT SURFACE  [IEC_HotSurface_Small]  (no BOM)
ESD_Susceptible1  ESD Susceptible  [ESD_Overlay_Small]  (no BOM)
FID1  Fiducial  [Fiducial10-20]  (value not drawn)  (no BOM)
FID2  Fiducial  [Fiducial10-20]  (value not drawn)  (no BOM)
FID3  Fiducial  [Fiducial10-20]  (value not drawn)  (no BOM)
FID4  Fiducial  [Fiducial10-20]  (value not drawn)  (no BOM)
FID5  Fiducial  [Fiducial10-20]  (value not drawn)  (no BOM)
FID6  Fiducial  [Fiducial10-20]  (value not drawn)  (no BOM)
FID7  Fiducial  [Fiducial10-20]  (value not drawn)  (no BOM)
FID8  Fiducial  [Fiducial10-20]  (value not drawn)  (no BOM)
FID9  Fiducial  [Fiducial10-20]  (value not drawn)  (no BOM)
FID10  Fiducial  [Fiducial10-20]  (value not drawn)  (no BOM)
FID11  Fiducial  [Fiducial10-20]  (value not drawn)  (no BOM)
FID12  Fiducial  [Fiducial10-20]  (value not drawn)  (no BOM)
FID13  Fiducial  [Fiducial10-20]  (value not drawn)  (no BOM)
FID14  Fiducial  [Fiducial10-20]  (value not drawn)  (no BOM)
FID15  Fiducial  [Fiducial10-20]  (value not drawn)  (no BOM)
FID16  Fiducial  [Fiducial10-20]  (value not drawn)  (no BOM)
LBL1  THT-14-423-10  Note: Size: 0.65" x 0.20 "  [Label_650x200]  (no BOM)
Logo1  Texas Instruments  [TI_Stacked_Overlay_Small]  (no BOM)
LOGO2  CE Mark  [CE_Mark_5mm]  (no BOM)
Logo3  FCC disclaimer  [FCC_disclaimer]  (no BOM)
Logo4  WEEE logo  [WEEE_Minimum]  (no BOM)
Logo5  UKCA Marking  [-UKCA_Filled]
ZZ1  This Assembly Note is for PCB labels only  [AssemblyNoteLabel]  (no BOM)
ZZ2  These assemblies are ESD sensitive, ESD precautions shall be observed.  [AssemblyNote]  (no BOM)
ZZ3  These assemblies must be clean and free from flux and all contaminants. Use of no clean flux is not acceptable.  [AssemblyNote]  (no BOM)
ZZ4  These assemblies must comply with workmanship standards IPC-A-610 Class 2, unless otherwise specified.  [AssemblyNote]  (no BOM)

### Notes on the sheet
- Variant
- Variant/Label Table
- Label Text
- 001
- AWR2E44PEVM

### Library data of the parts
!PCB = CMP-0003618-2: Manufacturer: Any; PartNumber: PROC196
CAUTION_HOT_SURFACE1 = CMP-0074837-1: IEC 61010-1 Hot Surface Warning; Library Reference: IEC_HotSurface; SymbolCreator: a0412235
ESD_Susceptible1 = CMP-0074840-1: ESD Susceptible Symbol; Library Reference: Logo; SymbolCreator: a0412235; Lib Reference: ESD_Susceptible
FID1-FID16 = CMP-0077181-1: Fiducial mark.  There is nothing to buy or mount.
LBL1 = CMP-0003625-1: Thermal Transfer Printable Labels, 0.650" W x 0.200" H - 10,000 per roll; Manufacturer: Brady; CompType: Label; Value: xWR2944EVM
Logo1 = CMP-0074838-1: Texas Instrument Corporate Signature; SymbolCreator: a0412235; Lib Reference: TI_Logo; Library Reference: Logo
LOGO2 = CMP-0074844-1: SymbolCreator: a0412235
Logo3 = CMP-0074847-1: FCC_disclaimer; Library Reference: Logo
Logo4 = CMP-0074769-1
Logo5 = CMP-0093808-1: Manufacturer: Texas Instruments
ZZ1 = CMP-0003616-3
ZZ2 = CMP-0077236-1
ZZ3 = CMP-0077237-1
ZZ4 = CMP-0077238-1

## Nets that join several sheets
1V0: PROC196A_IO_Reference (R133.2), PROC196A_PWR_Reference (U29.A5 U29.B5 U29.L1), PROC196A_Decoupling_Reference (6 pins), PROC196A_PMIC_Reference (R20.2), PROC196A_Current_Sensors (R56.1 R64.2 U22.8)
1V0_ETH: PROC196A_Ethernet_PWR (10 pins), PROC196A_Ethernet_PHY (U15.6 U15.24 U15.31 U15.42), PROC196A_Auto_Ethernet_PHY (FB2.1)
1V0_FILTERED: PROC196A_PMIC_Reference (6 pins), PROC196A_Current_Sensors (R64.1 R66.1)
1V2: PROC196A_IO_Reference (R315.2), PROC196A_PWR_Reference (18 pins), PROC196A_Decoupling_Reference (9 pins), PROC196A_PMIC_Reference (R70.2), PROC196A_Current_Sensors (R26.1 R30.2 U9.8)
1V4_APLL: PROC196A_PWR_Reference (U29.G2), PROC196A_Decoupling_Reference (C103.1)
1V4_SYNTH: PROC196A_PWR_Reference (U29.G1), PROC196A_Decoupling_Reference (C102.1)
1V8: PROC196A_IO_Reference (R156.2), PROC196A_PWR_Reference (12 pins), PROC196A_Decoupling_Reference (12 pins), PROC196A_PMIC_Reference (R67.2), PROC196A_Current_Sensors (R47.1 R60.2 U11.8)
1V8_FILTERED: PROC196A_PMIC_Reference (5 pins), PROC196A_Current_Sensors (R60.1 R65.1)
2V5_ETH: PROC196A_Ethernet_PWR (8 pins), PROC196A_Ethernet_PHY (U15.3 U15.9)
3V3: PROC196A_PWR_Reference (U29.A14 U29.J20 U29.T20 U29.U14), PROC196A_Decoupling_Reference (C174.2 C175.2 C176.2 C177.2), PROC196A_Current_Sensors (R346.2 R348.1 U12.8)
3V3_VIO: PROC196A_IO_Reference (8 pins), PROC196A_QSPI_Flash_Reference (5 pins), PROC196A_PMIC_Reference (R106.2 R116.2 R199.2), PROC196A_SOP_Reference (5 pins), PROC196A_PWR_RST_LED (5 pins), PROC196A_VPP_LDO (R409.2), PROC196A_Ethernet_PWR (R295.2), PROC196A_Auto_Ethernet_PHY (R28.1), PROC196A_CAN_Interface (8 pins), PROC196A_Current_Sensors (R346.1 R352.1)
5V0: PROC196A_PMIC_Reference (C119.1 C120.1 U8.10), PROC196A_PWR_RST_LED (R332.2), PROC196A_CAN_Interface (R16.2 R78.2)
FTDI_3V3: PROC196A_FTDI_PWR (R182.2), PROC196A_FTDI (17 pins)
GND: PROC196A_IO_Reference (24 pins), PROC196A_PWR_Reference (149 pins), PROC196A_Decoupling_Reference (34 pins), PROC196A_QSPI_Flash_Reference (C1.1 C2.1 U1.4 U1.9), PROC196A_PMIC_Reference (41 pins), PROC196A_3V3_Supply_Reference (15 pins), PROC196A_SOP_Reference (5 pins), PROC196A_PWR_RST_LED (18 pins), PROC196A_VPP_LDO (C145.2 C149.1 U27.2), PROC196A_Ethernet_PWR (27 pins), PROC196A_Ethernet_PHY (13 pins), PROC196A_Ethernet_Magnetics (11 pins), PROC196A_Auto_Ethernet_PHY (34 pins), PROC196A_Auto_Ethernet_conn (14 pins), PROC196A_FTDI_PWR (13 pins), PROC196A_FTDI (31 pins), PROC196A_XDS110 Interface_1A (18 pins), PROC196A_XDS110 Interface_1B (23 pins), PROC196A_JTAG_EMU_Connector (17 pins), PROC196A_Debug_Connector (18 pins), PROC196A_CAN_Interface (17 pins), PROC196A_Current_Sensors (9 pins), PROC196A_Temp_Sensor (C133.2 U24.2)
PMICOUT_1V2: PROC196A_PMIC_Reference (C129.1 C130.1 L2.2 R291.2), PROC196A_Current_Sensors (R30.1 R32.1)
PMICOUT_1V8: PROC196A_PMIC_Reference (5 pins), PROC196A_Ethernet_PWR (C60.1 U17.4 U17.6)
REGOUT_3V3: PROC196A_IO_Reference (C47.2 R416.2 U28.8), PROC196A_PMIC_Reference (L10.1 R199.1 R200.1), PROC196A_3V3_Supply_Reference (7 pins), PROC196A_VPP_LDO (C145.1 U27.1), PROC196A_Ethernet_PWR (C48.1 U16.6), PROC196A_Auto_Ethernet_PHY (FB1.1 R48.1), PROC196A_XDS110 Interface_1A (6 pins), PROC196A_XDS110 Interface_1B (20 pins), PROC196A_JTAG_EMU_Connector (6 pins), PROC196A_Debug_Connector (C18.2 R418.2 S2.1 U26.14), PROC196A_Current_Sensors (6 pins), PROC196A_Temp_Sensor (C133.1 R222.2 R317.1 U24.5)
VBAT_INT: PROC196A_3V3_Supply_Reference (5 pins), PROC196A_PWR_RST_LED (C99.1 C101.1 L5.2 R331.2), PROC196A_Auto_Ethernet_PHY (C197.1 R250.2 U33.1), PROC196A_CAN_Interface (C80.1 R52.2 U5.10)
VBGAP: PROC196A_PWR_Reference (U29.J1), PROC196A_Decoupling_Reference (C180.1)
VDDC_1: PROC196A_XDS110 Interface_1A (C62.1 C64.2 C74.2 C75.2), PROC196A_XDS110 Interface_1B (U6.87 U6.115)
VDDIO_ETH: PROC196A_Ethernet_PWR (8 pins), PROC196A_Ethernet_PHY (14 pins)
VPP_1P7: PROC196A_PWR_Reference (U29.U6), PROC196A_Decoupling_Reference (C150.2), PROC196A_VPP_LDO (P1.1)
XDSET_1_VBUS: PROC196A_XDS110 Interface_1A (C45.1 R161.2 U10.6), PROC196A_XDS110 Interface_1B (R154.2 R284.2)
3V3REG_EN: PROC196A_3V3_Supply_Reference (R6.2), PROC196A_CAN_Interface (U5.7)
AR_NERROUT: PROC196A_IO_Reference (R271.1 U29.B6), PROC196A_PMIC_Reference (R76.1), PROC196A_PWR_RST_LED (DS2.2), PROC196A_Debug_Connector (R379.1)
AR_NRST: PROC196A_IO_Reference (TP4.1 U29.C19), PROC196A_PMIC_Reference (R99.1), PROC196A_PWR_RST_LED (6 pins)
AR_NRST_FTDI: PROC196A_PWR_RST_LED (R268.1), PROC196A_FTDI (R166.2)
AR_NRST_XDS: PROC196A_PWR_RST_LED (R36.1), PROC196A_XDS110 Interface_1B (U6.40)
AR_SOP0_FTDI: PROC196A_SOP_Reference (R308.2), PROC196A_FTDI (R171.2)
AR_SOP1_FTDI: PROC196A_SOP_Reference (R304.2), PROC196A_FTDI (R170.2)
AR_SOP2_FTDI: PROC196A_SOP_Reference (R298.2), PROC196A_FTDI (R169.2)
AR_WRMRST: PROC196A_IO_Reference (R272.1 TP1.1 U29.A6), PROC196A_PWR_RST_LED (D5.2 D9.2), PROC196A_Debug_Connector (R371.1)
AR_WRMRST_FTDI: PROC196A_PWR_RST_LED (R362.1), PROC196A_FTDI (R330.2)
BSS_UARTA_TX: PROC196A_IO_Reference (R232.2 U29.J19), PROC196A_FTDI (R131.1)
CAN_nFAULT: PROC196A_IO_Reference (R233.2), PROC196A_CAN_Interface (U5.8)
CANA_NSTB: PROC196A_PMIC_Reference (R13.1), PROC196A_CAN_Interface (U32.2)
CANB_NSTB: PROC196A_PMIC_Reference (R17.1), PROC196A_CAN_Interface (R18.2 R19.1 U5.14)
CSI2_RX0_0_N: PROC196A_IO_Reference (U29.K18), PROC196A_JTAG_EMU_Connector (R192.1)
CSI2_RX0_0_P: PROC196A_IO_Reference (U29.K17), PROC196A_JTAG_EMU_Connector (R191.1)
CSI2_RX0_1_N: PROC196A_IO_Reference (U29.J18), PROC196A_JTAG_EMU_Connector (R189.1)
CSI2_RX0_1_P: PROC196A_IO_Reference (U29.J17), PROC196A_JTAG_EMU_Connector (R168.1)
CSI2_RX0_CLK_N: PROC196A_IO_Reference (U29.H18), PROC196A_JTAG_EMU_Connector (R138.1)
CSI2_RX0_CLK_P: PROC196A_IO_Reference (U29.H17), PROC196A_JTAG_EMU_Connector (R135.1)
DSS_UARTA_RX: PROC196A_IO_Reference (U29.A8), PROC196A_FTDI (R160.2)
DSS_UARTA_TX: PROC196A_IO_Reference (U29.A9), PROC196A_FTDI (R164.2)
EMU_TCK: PROC196A_JTAG_EMU_Connector (R244.1 R354.1 R375.2), PROC196A_Debug_Connector (R422.1)
EMU_TDI: PROC196A_JTAG_EMU_Connector (R356.1 R376.2), PROC196A_Debug_Connector (R423.1)
EMU_TDO: PROC196A_JTAG_EMU_Connector (J19.4 R360.1), PROC196A_Debug_Connector (R425.2)
EMU_TMS: PROC196A_JTAG_EMU_Connector (R358.1 R374.1), PROC196A_Debug_Connector (R424.2)
ETH1_INT_PWDN: PROC196A_IO_Reference (R224.2), PROC196A_Ethernet_PHY (R340.1 U15.44)
ETH1_NRST: PROC196A_IO_Reference (R229.2), PROC196A_Ethernet_PHY (R342.1 U15.43)
ETH2_INT: PROC196A_IO_Reference (R22.1), PROC196A_Auto_Ethernet_PHY (R34.2 U4.2)
ETH2_NRST: PROC196A_IO_Reference (R23.1), PROC196A_Auto_Ethernet_PHY (R46.2 U4.3)
ETH_LED0: PROC196A_Ethernet_PHY (R92.1 R97.2 U15.47), PROC196A_Ethernet_Magnetics (R68.1)
ETH_LED2: PROC196A_Ethernet_PHY (R132.1 R137.2 U15.45), PROC196A_Ethernet_Magnetics (R69.2)
ETH_TRD_N: PROC196A_Auto_Ethernet_PHY (U4.13), PROC196A_Auto_Ethernet_conn (C156.2 R265.1)
ETH_TRD_P: PROC196A_Auto_Ethernet_PHY (U4.12), PROC196A_Auto_Ethernet_conn (C162.1 R270.1)
FTDI_USBD_N: PROC196A_FTDI_PWR (J10.2 U21.1), PROC196A_FTDI (U18.7)
FTDI_USBD_P: PROC196A_FTDI_PWR (J10.3 U21.2), PROC196A_FTDI (U18.8)
GPADC1: PROC196A_IO_Reference (C136.2 R316.1 U29.K2), PROC196A_Debug_Connector (R80.1)
GPADC2: PROC196A_IO_Reference (C135.2 R315.1 U29.K1), PROC196A_Debug_Connector (R82.1)
GPADC3: PROC196A_IO_Reference (C131.2 R133.1 U29.N1), PROC196A_Debug_Connector (R83.1)
GPADC5: PROC196A_IO_Reference (U29.M2), PROC196A_Debug_Connector (R91.1)
GPADC6: PROC196A_IO_Reference (U29.L2), PROC196A_Debug_Connector (R94.1)
LVDS_TX0_N: PROC196A_IO_Reference (U29.D20), PROC196A_Debug_Connector (R366.2)
LVDS_TX0_P: PROC196A_IO_Reference (U29.D19), PROC196A_Debug_Connector (R365.2)
LVDS_TX1_N: PROC196A_IO_Reference (U29.H20), PROC196A_Debug_Connector (R364.2)
LVDS_TX1_P: PROC196A_IO_Reference (U29.H19), PROC196A_Debug_Connector (R363.2)
LVDS_TX2_CLK_N: PROC196A_IO_Reference (U29.E20), PROC196A_Debug_Connector (R349.2 R361.2)
LVDS_TX2_CLK_P: PROC196A_IO_Reference (U29.E19), PROC196A_Debug_Connector (R345.2 R351.2)
LVDS_TX3_FRCLK_N: PROC196A_IO_Reference (U29.G20), PROC196A_Debug_Connector (R323.2 R341.2)
LVDS_TX3_FRCLK_P: PROC196A_IO_Reference (U29.G19), PROC196A_Debug_Connector (R322.2 R327.2)
MCU_CLKOUT: PROC196A_IO_Reference (R165.2), PROC196A_Debug_Connector (R115.1)
MSS_EPWMA0: PROC196A_IO_Reference (U29.A18), PROC196A_Debug_Connector (R81.1)
MSS_EPWMA1: PROC196A_IO_Reference (R213.2), PROC196A_Debug_Connector (R198.1)
MSS_EPWMB0: PROC196A_IO_Reference (R213.1 U29.C17), PROC196A_Debug_Connector (R197.1)
MSS_GPIO_1: PROC196A_IO_Reference (U29.A10), PROC196A_Debug_Connector (R329.1)
MSS_GPIO_2: PROC196A_IO_Reference (U29.C20), PROC196A_PWR_RST_LED (R347.2)
MSS_GPIO_3: PROC196A_IO_Reference (R219.2), PROC196A_Debug_Connector (R114.1)
MSS_GPIO_11: PROC196A_IO_Reference (R236.2 U29.K19), PROC196A_CAN_Interface (R54.1)
MSS_GPIO_28: PROC196A_IO_Reference (U29.P19), PROC196A_PWR_RST_LED (R334.2)
MSS_I2CA_SCL: PROC196A_IO_Reference (6 pins), PROC196A_FTDI (R148.2), PROC196A_Debug_Connector (R390.1), PROC196A_Current_Sensors (R27.2 R33.2 R57.2 R58.2), PROC196A_Temp_Sensor (R318.1)
MSS_I2CA_SDA: PROC196A_IO_Reference (6 pins), PROC196A_FTDI (R149.2 R150.2), PROC196A_Debug_Connector (R391.1), PROC196A_Current_Sensors (R29.2 R35.2 R59.2 R62.2), PROC196A_Temp_Sensor (R319.2)
MSS_MCANA_RX: PROC196A_IO_Reference (U29.B18), PROC196A_CAN_Interface (R12.1)
MSS_MCANA_TX: PROC196A_IO_Reference (U29.C18), PROC196A_CAN_Interface (R11.1)
MSS_MCANB_RX: PROC196A_IO_Reference (U29.A17), PROC196A_CAN_Interface (R25.1)
MSS_MCANB_TX: PROC196A_IO_Reference (U29.A15), PROC196A_CAN_Interface (R21.1)
MSS_MDIO_CLK: PROC196A_IO_Reference (U29.U2), PROC196A_Ethernet_PHY (R369.1), PROC196A_Auto_Ethernet_PHY (R249.1)
MSS_MDIO_DATA: PROC196A_IO_Reference (R280.1 U29.T2), PROC196A_Ethernet_PHY (R413.1), PROC196A_Auto_Ethernet_PHY (R247.1)
MSS_RGMII_RCLK: PROC196A_IO_Reference (U29.T5), PROC196A_Ethernet_PHY (R290.1), PROC196A_Auto_Ethernet_PHY (R234.1)
MSS_RGMII_RCTL: PROC196A_IO_Reference (U29.T7), PROC196A_Ethernet_PHY (R195.1 R211.1 R289.2), PROC196A_Auto_Ethernet_PHY (R245.1)
MSS_RGMII_RD0: PROC196A_IO_Reference (U29.T3), PROC196A_Ethernet_PHY (R173.1 R287.2 R325.1), PROC196A_Auto_Ethernet_PHY (R237.1)
MSS_RGMII_RD1: PROC196A_IO_Reference (U29.U4), PROC196A_Ethernet_PHY (R336.1), PROC196A_Auto_Ethernet_PHY (R238.1)
MSS_RGMII_RD2: PROC196A_IO_Reference (U29.T4), PROC196A_Ethernet_PHY (R286.1 R288.2 R338.1), PROC196A_Auto_Ethernet_PHY (R239.1)
MSS_RGMII_RD3: PROC196A_IO_Reference (U29.U5), PROC196A_Ethernet_PHY (R339.1), PROC196A_Auto_Ethernet_PHY (R240.1)
MSS_RGMII_TCLK: PROC196A_IO_Reference (U29.T6), PROC196A_Ethernet_PHY (R98.1), PROC196A_Auto_Ethernet_PHY (R74.1)
MSS_RGMII_TCTL: PROC196A_IO_Reference (U29.U9), PROC196A_Ethernet_PHY (R101.1), PROC196A_Auto_Ethernet_PHY (R230.1)
MSS_RGMII_TD0: PROC196A_IO_Reference (U29.U7), PROC196A_Ethernet_PHY (R103.1), PROC196A_Auto_Ethernet_PHY (R96.1)
MSS_RGMII_TD1: PROC196A_IO_Reference (U29.U10), PROC196A_Ethernet_PHY (R105.1), PROC196A_Auto_Ethernet_PHY (R100.1)
MSS_RGMII_TD2: PROC196A_IO_Reference (U29.R12), PROC196A_Ethernet_PHY (R121.1), PROC196A_Auto_Ethernet_PHY (R178.1)
MSS_RGMII_TD3: PROC196A_IO_Reference (U29.T12), PROC196A_Ethernet_PHY (R122.1), PROC196A_Auto_Ethernet_PHY (R225.1)
MSS_RS232RX: PROC196A_IO_Reference (R278.1 U29.B19), PROC196A_FTDI (R158.2)
MSS_RS232TX: PROC196A_IO_Reference (R279.1 U29.A19), PROC196A_FTDI (R162.2)
MSS_SPIA_CLK: PROC196A_IO_Reference (U29.T18), PROC196A_FTDI (R144.2)
MSS_SPIA_CS0: PROC196A_IO_Reference (U29.U18), PROC196A_FTDI (R147.2)
MSS_SPIA_HOSTIRQ: PROC196A_IO_Reference (R109.1 R326.2), PROC196A_FTDI (R151.2 R153.2), PROC196A_Debug_Connector (R320.1)
MSS_SPIA_MISO: PROC196A_IO_Reference (R392.1), PROC196A_FTDI (R146.2)
MSS_SPIA_MOSI: PROC196A_IO_Reference (U29.U17), PROC196A_FTDI (R145.2)
MSS_SPIB_CLK: PROC196A_IO_Reference (R380.1), PROC196A_Debug_Connector (U26.2)
MSS_SPIB_CS0: PROC196A_IO_Reference (R273.1 U29.U15), PROC196A_Debug_Connector (U26.10)
MSS_SPIB_CS1: PROC196A_IO_Reference (R107.1), PROC196A_Debug_Connector (R215.1)
MSS_SPIB_MISO: PROC196A_IO_Reference (U29.T15), PROC196A_Debug_Connector (U26.5)
MSS_SPIB_MOSI: PROC196A_IO_Reference (R381.1), PROC196A_Debug_Connector (U26.7)
MSS_UARTA_RX: PROC196A_IO_Reference (U29.A16), PROC196A_XDS110 Interface_1B (R129.1)
OSC_CLK_OUT_ETH: PROC196A_IO_Reference (R88.1), PROC196A_Auto_Ethernet_PHY (R259.1)
OSC_CLKTOP: PROC196A_IO_Reference (R90.1 U29.B1), PROC196A_Auto_Ethernet_PHY (R367.1)
PMIC_CLK: PROC196A_PMIC_Reference (R75.1), PROC196A_SOP_Reference (R297.2)
PMIC_EN: PROC196A_PMIC_Reference (R125.1 R185.2 U8.15), PROC196A_3V3_Supply_Reference (R4.1)
PMIC_NINT: PROC196A_IO_Reference (R214.2), PROC196A_PMIC_Reference (5 pins)
PMIC_SPI_CLK: PROC196A_PMIC_Reference (R63.2 R167.1), PROC196A_Debug_Connector (U26.16)
PMIC_SPI_CS0: PROC196A_PMIC_Reference (R5.1 R190.1), PROC196A_Debug_Connector (U26.12)
PMIC_SPI_MISO: PROC196A_PMIC_Reference (R176.1 R193.2), PROC196A_Debug_Connector (U26.3)
PMIC_SPI_MOSI: PROC196A_PMIC_Reference (R61.2 R186.2), PROC196A_Debug_Connector (U26.9)
QSPI_CS: PROC196A_IO_Reference (U29.T1), PROC196A_QSPI_Flash_Reference (R38.1 U1.1)
QSPI_D0: PROC196A_IO_Reference (U29.P2), PROC196A_QSPI_Flash_Reference (R45.2)
QSPI_D1: PROC196A_IO_Reference (U29.N2), PROC196A_QSPI_Flash_Reference (R39.1 R49.1)
QSPI_D2: PROC196A_IO_Reference (U29.P1), PROC196A_QSPI_Flash_Reference (R42.1 R43.1)
QSPI_D3: PROC196A_IO_Reference (U29.R1), PROC196A_QSPI_Flash_Reference (R40.2 R41.1)
QSPI_SCLK: PROC196A_IO_Reference (U29.R2), PROC196A_QSPI_Flash_Reference (R44.2)
SOP0_TDO: PROC196A_IO_Reference (R386.1), PROC196A_SOP_Reference (R310.1), PROC196A_JTAG_EMU_Connector (U23.10)
SOP1_MSS_SPIB_CS2: PROC196A_IO_Reference (U29.T17), PROC196A_SOP_Reference (R305.1), PROC196A_Debug_Connector (R324.1)
SOP2_PMIC_CLK: PROC196A_IO_Reference (R218.2), PROC196A_SOP_Reference (R297.1 R299.1)
SOP3_MSS_GPIO_0: PROC196A_IO_Reference (R212.1 U29.B7), PROC196A_Debug_Connector (R328.1)
SOP3_MSS_UARTB_TX: PROC196A_IO_Reference (R212.2), PROC196A_SOP_Reference (R301.1 R303.2), PROC196A_XDS110 Interface_1B (R136.1)
SOP4_MSS_UARTA_TX: PROC196A_IO_Reference (U29.B17), PROC196A_SOP_Reference (R309.1 R312.2), PROC196A_XDS110 Interface_1B (R128.1)
TCK: PROC196A_IO_Reference (U29.B8), PROC196A_JTAG_EMU_Connector (U23.2)
TD_1_N: PROC196A_Ethernet_PHY (U15.2), PROC196A_Ethernet_Magnetics (J9.10 U13.2 U13.9)
TD_1_P: PROC196A_Ethernet_PHY (U15.1), PROC196A_Ethernet_Magnetics (J9.9 U13.1 U13.10)
TD_2_N: PROC196A_Ethernet_PHY (U15.5), PROC196A_Ethernet_Magnetics (J9.8 U13.5 U13.6)
TD_2_P: PROC196A_Ethernet_PHY (U15.4), PROC196A_Ethernet_Magnetics (J9.7 U13.4 U13.7)
TD_3_N: PROC196A_Ethernet_PHY (U15.8), PROC196A_Ethernet_Magnetics (J9.6 U14.2 U14.9)
TD_3_P: PROC196A_Ethernet_PHY (U15.7), PROC196A_Ethernet_Magnetics (J9.5 U14.1 U14.10)
TD_4_N: PROC196A_Ethernet_PHY (U15.11), PROC196A_Ethernet_Magnetics (J9.4 U14.5 U14.6)
TD_4_P: PROC196A_Ethernet_PHY (U15.10), PROC196A_Ethernet_Magnetics (J9.3 U14.4 U14.7)
TDI: PROC196A_IO_Reference (U29.B9), PROC196A_JTAG_EMU_Connector (U23.5)
TMS: PROC196A_IO_Reference (U29.B10), PROC196A_JTAG_EMU_Connector (U23.7)
TRACE_CLK: PROC196A_IO_Reference (R216.2), PROC196A_JTAG_EMU_Connector (R72.1 R226.1)
TRACE_CTL: PROC196A_IO_Reference (R220.2), PROC196A_JTAG_EMU_Connector (J19.17)
TRACE_DATA0: PROC196A_IO_Reference (R227.1), PROC196A_JTAG_EMU_Connector (J19.19)
TRACE_DATA1: PROC196A_IO_Reference (R231.1), PROC196A_JTAG_EMU_Connector (J19.21)
TRACE_DATA2: PROC196A_IO_Reference (R235.1), PROC196A_JTAG_EMU_Connector (J19.23)
TRACE_DATA3: PROC196A_IO_Reference (R217.1), PROC196A_JTAG_EMU_Connector (J19.25)
TRACE_DATA4: PROC196A_IO_Reference (R221.1), PROC196A_JTAG_EMU_Connector (J19.27)
TRACE_DATA5: PROC196A_IO_Reference (R228.1), PROC196A_JTAG_EMU_Connector (J19.29)
TRACE_DATA6: PROC196A_IO_Reference (R232.1), PROC196A_JTAG_EMU_Connector (J19.31)
TRACE_DATA7: PROC196A_IO_Reference (R236.1), PROC196A_JTAG_EMU_Connector (J19.33)
VPP_EN: PROC196A_IO_Reference (U29.U3), PROC196A_VPP_LDO (R159.1)
XDS_TCK: PROC196A_XDS110 Interface_1B (R387.1), PROC196A_JTAG_EMU_Connector (R353.1)
XDS_TDI: PROC196A_XDS110 Interface_1B (R389.1), PROC196A_JTAG_EMU_Connector (R355.1)
XDS_TDO: PROC196A_XDS110 Interface_1B (U6.37), PROC196A_JTAG_EMU_Connector (R359.1)
XDS_TMS: PROC196A_XDS110 Interface_1B (R388.1), PROC196A_JTAG_EMU_Connector (R357.1)
XDSET_1_D_N: PROC196A_XDS110 Interface_1A (J8.2 U10.1), PROC196A_XDS110 Interface_1B (U6.93)
XDSET_1_D_P: PROC196A_XDS110 Interface_1A (J8.3 U10.2), PROC196A_XDS110 Interface_1B (U6.94)
XDSET_1_ID: PROC196A_XDS110 Interface_1A (J8.4 U10.4), PROC196A_XDS110 Interface_1B (R152.1)
XREF_CLK0: PROC196A_IO_Reference (U29.A7), PROC196A_Debug_Connector (R84.1)

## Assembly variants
001: not fitted C4 C7 C32 C37 C120 C122 C127 C151 C152 C155 C156 C162 C166 C169 C194 C196 C197 C198 D3 D7 D8 D10 D14 D18 D19 J1 J5 J13 J16 J21 J22 J23 L10 R4 R5 R6 R8 R10 R19 R20 R22 R23 R28 R61 R67 R70 R72 R74 R77 R79 R80 R82 R83 R89 R92 R93 R95 R96 R97 R100 R102 R107 R108 R112 R113 R114 R117 R118 R119 R120 R130 R132 R135 R137 R138 R139 R141 R142 R143 R159 R160 R164 R167 R168 R173 R176 R177 R178 R185 R189 R191 R192 R197 R198 R199 R204 R210 R213 R214 R216 R217 R220 R221 R224 R225 R226 R227 R228 R229 R230 R231 R232 R234 R235 R236 R237 R238 R239 R240 R244 R245 R247 R249 R250 R252 R253 R254 R258 R259 R260 R269 R274 R286 R287 R288 R297 R303 R312 R314 R320 R324 R327 R328 R341 R345 R349 R350 R367 R371 R379 R416 R417 R422 R423 R424 R425 U33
